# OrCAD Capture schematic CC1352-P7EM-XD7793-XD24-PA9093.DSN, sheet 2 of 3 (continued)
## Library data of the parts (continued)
L33 L42 = INDUCTOR_HOR_1_2: INDUCTOR, RF, CHIP, NON-MAGNETIC CORE, 10nH, -5%/+5%, 0.3A, -55DEGC/+125DEGC, 0402, SMD; ALT_SYMBOLS: INDC1005X60C2L,INDC1005X60C2M; Additional Datasheet URL: https://search.murata.co.jp/Ceramy/image/img/P02/JELF243B-0010.pdf; Budgetary Price: 0.03 EUR; Country of Origin: Japan,Singapore; Datasheet URL: https://www.murata.com/~/media/webrenewal/support/library/catalog/products/inductor/chip/o05e.ashx?la=en-gb; FPLIST: INDC1005X60C2N,INDC1005X60D2N; Frequency: 3.4GHz; Lead Time: 9; Mass: 0.001g; Maximum Operating Temperature: +125DEGC; Maximum Tolerance: +5%; Minimum Operating Temperature: -55DEGC; Minimum Tolerance: -5%; Mounting Type: SMD; NOTEfied URL: https://notefied-dynamic-precision.com/NOTEfiedWebInterface/part/show?partNumber=03-06635; PCB Package: 0402; Packing Size: 10000; Packing Type: Tape & Reel; Part Number: 03-06635; Part Type: Inductor|RF|CHIP|0402; REACH/SVHC Compliance: Compliant; REACH/SVHC Details: SVHC List Version Jul 7, 2017; REACH/SVHC Source: REACH Declaration; REACH/SVHC Status: Unaffected; ROHS: Compliant; Resistance: 0.26; Revision: R016; Status: Released; Texas Part Status: Under Review; Type: Inductor; Vendor: MURATA; Vendor Part Number: LQG15HS10NJ02D; Vendor Part Status: Active
L34 = INDUCTOR_HOR_1_2: INDUCTOR, RF, CHIP, NON-MAGNETIC CORE, 7.5nH, -5%/+5%, 0.3A, -55DEGC/+125DEGC, 0402, SMD; Additional Datasheet URL: https://search.murata.co.jp/Ceramy/image/img/P02/JELF243B-0010.pdf; Budgetary Price: 0.03 EUR; Country of Origin: Missing Info; Datasheet URL: https://www.murata.com/~/media/webrenewal/support/library/catalog/products/inductor/chip/o05e.ashx?la=en-gb; Frequency: 4.2GHz; Lead Time: 10; Mass: 0.001g; Maximum Operating Temperature: +125DEGC; Maximum Tolerance: +5%; Minimum Operating Temperature: -55DEGC; Minimum Tolerance: -5%; Mounting Type: SMD; NOTEfied URL: https://notefied-dynamic-precision.com/NOTEfiedWebInterface/part/show?partNumber=03-07022; PCB Package: 0402; Packing Size: 10000; Packing Type: Tape & Reel; Part Number: 03-07022; Part Type: Inductor|RF|CHIP|0402; REACH/SVHC Compliance: Compliant; REACH/SVHC Details: SVHC List Version Jul 7, 2017; REACH/SVHC Source: REACH Declaration; REACH/SVHC Status: Unaffected; ROHS: Compliant; Resistance: 0.24; Revision: R017; Status: Released; Texas Part Status: Under Review; Type: Inductor; Vendor: MURATA; Vendor Part Number: LQG15HS7N5J02D; Vendor Part Status: Active
L51 L61 = INDUCTOR_HOR_1_2: INDUCTOR, RF, CHIP, NON-MAGNETIC CORE, 1nH, -0.3nH/+0.3nH, 0.3A, -55DEGC/+125DEGC, 0402, SMD; ALT_SYMBOLS: INDC1005X60C2L,INDC1005X60C2M; Additional Datasheet URL: https://search.murata.co.jp/Ceramy/image/img/P02/JELF243B-0010.pdf; Budgetary Price: 0.031 EUR; Country of Origin: Japan,Singapore; Datasheet URL: https://www.murata.com/~/media/webrenewal/support/library/catalog/products/inductor/chip/o05e.ashx?la=en-gb; Frequency: 10GHz; Lead Time: 9; Mass: 0.001g; Maximum Operating Temperature: +125DEGC; Maximum Tolerance: +0.3nH; Minimum Operating Temperature: -55DEGC; Minimum Tolerance: -0.3nH; Mounting Type: SMD; NOTEfied URL: https://notefied-dynamic-precision.com/NOTEfiedWebInterface/part/show?partNumber=03-07676; PCB Package: 0402; Packing Size: 10000; Packing Type: Tape & Reel; Part Number: 03-07676; Part Type: Inductor|RF|CHIP|0402; REACH/SVHC Compliance: Compliant; REACH/SVHC Details: SVHC List Version Jul 7, 2017; REACH/SVHC Source: REACH Declaration; REACH/SVHC Status: Unaffected; ROHS: Compliant; Resistance: 0.07; Revision: R018; Status: Released; Texas Part Status: Under Review; Type: Inductor; Vendor: MURATA; Vendor Part Number: LQG15HS1N0S02D; Vendor Part Status: Active
L52 = INDUCTOR_HOR_1_2: INDUCTOR, RF, CHIP, NON-MAGNETIC CORE, 27nH, -5%/+5%, 0.3A, -55DEGC/+125DEGC, 0402, SMD; Additional Datasheet URL: https://search.murata.co.jp/Ceramy/image/img/P02/JELF243B-0010.pdf; Budgetary Price: 0.03 EUR; Country of Origin: Japan,Singapore; Datasheet URL: https://www.murata.com/~/media/webrenewal/support/library/catalog/products/inductor/chip/o05e.ashx?la=en-gb; Exclusive for Customers: TEXAS INSTRUMENTS NORWAY; Frequency: 1700MHz; Lead Time: 9; Mass: 0.001g; Maximum Operating Temperature: +125DEGC; Maximum Tolerance: +5%; Minimum Operating Temperature: -55DEGC; Minimum Tolerance: -5%; Mounting Type: SMD; NOTEfied URL: https://notefied-dynamic-precision.com/NOTEfiedWebInterface/part/show?partNumber=03-07528; Notes: Standard item: Duplicate Reason: custom footprint for TEXAS INSTRUMENTS NORWAY.; PCB Package: 0402; Packing Size: 10000; Packing Type: Tape & Reel; Part Number: 03-07528; Part Type: Inductor|RF|CHIP|0402; REACH/SVHC Compliance: Compliant; REACH/SVHC Details: SVHC List Version Jul 7, 2017; REACH/SVHC Source: REACH Declaration; REACH/SVHC Status: Unaffected; ROHS: Compliant; Resistance: 0.46; Revision: R018; Status: Released; Texas Part Status: Under Review; Type: Inductor; Vendor: MURATA; Vendor Part Number: LQG15HS27NJ02D; Vendor Part Status: Active
L53 L62 = INDUCTOR: INDUCTOR, RF, CHIP, NON-MAGNETIC CORE, 12nH, -5%/+5%, 0.5A, -55DEGC/+125DEGC, 0402, SMD; ALT_SYMBOLS: INDC1005X60A2L,INDC1005X60A2M; Additional Datasheet URL: https://search.murata.co.jp/Ceramy/image/img/P02/JELF243A-0050.pdf; AutoDoc File: https://notefied-dynamic-precision.com/DB/Apps/Desktop/Item/Object.aspx?id=86088; BU Name: DYNAMIC PRECISION GDANSK; Budget Currency: EUR; Budget Price: 0.144; Budgetary Price: 0.144 EUR; Client Status: UNDER_REVIEW; Core Material: NON-MAGNETIC; Country of Origin: Japan,Singapore; Datasheet URL: https://www.murata.com/~/media/webrenewal/support/library/catalog/products/inductor/chip/o05e.ashx?la=en-gb; Datasheet URL 1: http://psearch.murata.com/inductor/product/LQW15AN12NJ00%23.pdf; Datasheet URL 2: http://www.murata.com/~/media/webrenewal/support/library/catalog/products/inductor/chip/o05e.ashx; FPLIST: INDC1005X60A2N,INDC1005X60B2N; Frequency: 5.5GHz; Lead Time: 9; Mass: 0.0008g; Max Oper Temp: +125DEGC; Max Tol: +5%; Maximum Operating Temperature: +125DEGC; Maximum Tolerance: +5%; Min Oper Temp: -55DEGC; Min Tol: -5%; Minimum Operating Temperature: -55DEGC; Minimum Tolerance: -5%; Mounting Type: SMD; NOTEfied URL: https://notefied-dynamic-precision.com/NOTEfiedWebInterface/part/show?partNumber=03-06556; PCB Package: 0402; Packing Size: 10000; Packing Type: Tape & Reel; Part Number: 03-06556; Part Type: Inductor|RF|CHIP|0402; REACH/SVHC Compliance: Compliant; REACH/SVHC Details: SVHC List Version Jul 7, 2017; REACH/SVHC Source: REACH Declaration; REACH/SVHC Status: Unaffected; REACH/SVHC_COMPLIANCE: COMPLIANT; REACH/SVHC_DETAILS: SVHC LIST VERSION Dec 17, 2015; REACH/SVHC_SOURCE: REACH DECLARATION; REACH/SVHC_STATUS: UNAFFECTED; ROHS: Compliant; Resistance: 0.14; Revision: R021; RoHS Status: ROHS_COMPLIANT; Rtd Current: 0.5A; Status: Released; Texas Part Status: Under Review; Type: Inductor; Vendor: MURATA; Vendor Part Number: LQW15AN12NJ00D; Vendor Part Status: Active; Weight: 0.0008g
L54 = INDUCTOR: INDUCTOR, RF, CHIP, NON-MAGNETIC CORE, 4.3nH, -0.2nH/+0.2nH, 0.75A, -55DEGC/+125DEGC, 0402, SMD; ALT_SYMBOLS: INDC1005X60A2L,INDC1005X60A2M; Additional Datasheet URL: https://search.murata.co.jp/Ceramy/image/img/P02/JELF243A-0050.pdf; AutoDoc File: https://notefied-dynamic-precision.com/DB/Apps/Desktop/Item/Object.aspx?id=88050; BU Name: DYNAMIC PRECISION GDANSK; Budget Currency: EUR; Budget Price: 0.151; Budgetary Price: 0.151 EUR; Client Status: UNDER_REVIEW; Core Material: NON-MAGNETIC; Country of Origin: Japan,Singapore; Datasheet URL: https://www.murata.com/~/media/webrenewal/support/library/catalog/products/inductor/chip/o05e.ashx?la=en-gb; Datasheet URL 1: http://psearch.murata.com/inductor/product/LQW15AN4N3C00%23.pdf; Datasheet URL 2: http://www.murata.com/~/media/webrenewal/support/library/catalog/products/inductor/chip/o05e.ashx; FPLIST: INDC1005X60A2N,INDC1005X60B2N; Frequency: 10GHz; Lead Time: 9; Mass: 0.0008g; Max Oper Temp: +125DEGC; Max Tol: +0.2nH; Maximum Operating Temperature: +125DEGC; Maximum Tolerance: +0.2nH; Min Oper Temp: -55DEGC; Min Tol: -0.2nH; Minimum Operating Temperature: -55DEGC; Minimum Tolerance: -0.2nH; Mounting Type: SMD; NOTEfied URL: https://notefied-dynamic-precision.com/NOTEfiedWebInterface/part/show?partNumber=03-06658; PCB Package: 0402; Packing Size: 10000; Packing Type: Tape & Reel; Part Number: 03-06658; Part Type: Inductor|RF|CHIP|0402; REACH/SVHC Compliance: Compliant; REACH/SVHC Details: SVHC List Version Jan 15, 2018; REACH/SVHC Source: REACH Declaration; REACH/SVHC Status: Unaffected; ROHS: Compliant; Resistance: 0.07; Revision: R019; RoHS Status: ROHS_COMPLIANT; Rtd Current: 0.75A; Status: Released; Texas Part Status: Under Review; Type: Inductor; Vendor: MURATA; Vendor Part Number: LQW15AN4N3C00D; Vendor Part Status: Active; Weight: 0.0008g
L55 = INDUCTOR: INDUCTOR, RF, CHIP, NON-MAGNETIC CORE, 2.5nH, -0.2nH/+0.2nH, 0.85A, -55DEGC/+125DEGC, 0402, SMD; ALT_SYMBOLS: INDC1005X60A2L,INDC1005X60A2M; Additional Datasheet URL: https://search.murata.co.jp/Ceramy/image/img/P02/JELF243A-0050.pdf; AutoDoc File: https://notefied-dynamic-precision.com/DB/Apps/Desktop/Item/Object.aspx?id=88045; BU Name: DYNAMIC PRECISION GDANSK; Budget Currency: EUR; Budget Price: 0.151; Budgetary Price: 0.151 EUR; Client Status: UNDER_REVIEW; Core Material: NON-MAGNETIC; Country of Origin: Japan,Singapore; Datasheet URL: https://www.murata.com/~/media/webrenewal/support/library/catalog/products/inductor/chip/o05e.ashx?la=en-gb; Datasheet URL 1: http://psearch.murata.com/inductor/product/LQW15AN2N5C00%23.pdf; Datasheet URL 2: http://www.murata.com/~/media/webrenewal/support/library/catalog/products/inductor/chip/o05e.ashx; FPLIST: INDC1005X60A2N,INDC1005X60B2N; Frequency: 15GHz; Lead Time: 10; Mass: 0.0008g; Max Oper Temp: +125DEGC; Max Tol: +0.2nH; Maximum Operating Temperature: +125DEGC; Maximum Tolerance: +0.2nH; Min Oper Temp: -55DEGC; Min Tol: -0.2nH; Minimum Operating Temperature: -55DEGC; Minimum Tolerance: -0.2nH; Mounting Type: SMD; NOTEfied URL: https://notefied-dynamic-precision.com/NOTEfiedWebInterface/part/show?partNumber=03-06653; PCB Package: 0402; Packing Size: 10000; Packing Type: Tape & Reel; Part Number: 03-06653; Part Type: Inductor|RF|CHIP|0402; REACH/SVHC Compliance: Compliant; REACH/SVHC Details: SVHC List Version Jan 15, 2018; REACH/SVHC Source: REACH Declaration; REACH/SVHC Status: Unaffected; ROHS: Compliant; Resistance: 0.05; Revision: R020; RoHS Status: ROHS_COMPLIANT; Rtd Current: 0.85A; Status: Released; Texas Part Status: Under Review; Type: Inductor; Vendor: MURATA; Vendor Part Number: LQW15AN2N5C00D; Vendor Part Status: Active; Weight: 0.0008g
L56 = INDUCTOR: INDUCTOR, RF, CHIP, NON-MAGNETIC CORE, 4.7nH, -0.2nH/+0.2nH, 0.75A, -55DEGC/+125DEGC, 0402, SMD; ALT_SYMBOLS: INDC1005X60A2L,INDC1005X60A2M; Additional Datasheet URL: https://search.murata.co.jp/Ceramy/image/img/P02/JELF243A-0050.pdf; AutoDoc File: https://notefied-dynamic-precision.com/DB/Apps/Desktop/Item/Object.aspx?id=88051; BU Name: DYNAMIC PRECISION GDANSK; Budget Currency: EUR; Budget Price: 0.152; Budgetary Price: 0.152 EUR; Client Status: UNDER_REVIEW; Core Material: NON-MAGNETIC; Country of Origin: Japan,Singapore; Datasheet URL: https://www.murata.com/~/media/webrenewal/support/library/catalog/products/inductor/chip/o05e.ashx?la=en-gb; Datasheet URL 1: http://psearch.murata.com/inductor/product/LQW15AN4N7C00%23.pdf; Datasheet URL 2: http://www.murata.com/~/media/webrenewal/support/library/catalog/products/inductor/chip/o05e.ashx; FPLIST: INDC1005X60A2N,INDC1005X60B2N; Frequency: 8GHz; Lead Time: 9; Mass: 0.0008g; Max Oper Temp: +125DEGC; Max Tol: +0.2nH; Maximum Operating Temperature: +125DEGC; Maximum Tolerance: +0.2nH; Min Oper Temp: -55DEGC; Min Tol: -0.2nH; Minimum Operating Temperature: -55DEGC; Minimum Tolerance: -0.2nH; Mounting Type: SMD; NOTEfied URL: https://notefied-dynamic-precision.com/NOTEfiedWebInterface/part/show?partNumber=03-06659; PCB Package: 0402; Packing Size: 10000; Packing Type: Tape & Reel; Part Number: 03-06659; Part Type: Inductor|RF|CHIP|0402; REACH/SVHC Compliance: Compliant; REACH/SVHC Details: SVHC List Version Jan 15, 2018; REACH/SVHC Source: REACH Declaration; REACH/SVHC Status: Unaffected; ROHS: Compliant; Resistance: 0.07; Revision: R019; RoHS Status: ROHS_COMPLIANT; Rtd Current: 0.75A; Status: Released; Texas Part Status: Under Review; Type: Inductor; Vendor: MURATA; Vendor Part Number: LQW15AN4N7C00D; Vendor Part Status: Active; Weight: 0.0008g
L331 = INDUCTOR: INDUCTOR, STANDARD, FERRITE CORE, 6.8uH, -20%/+20%, 0.11A, -55DEGC/+125DEGC, 0805, SMD; ALT_SYMBOLS: INDC2012X150A2L,INDC2012X150A2M; Additional Datasheet URL: https://product.tdk.com/en/search/inductor/inductor/smd/info?part_no=MLZ2012N6R8LT000; AutoDoc File: https://notefied-dynamic-precision.com/DB/Apps/Desktop/Item/Object.aspx?id=102853; BU Name: DYNAMIC PRECISION GDANSK; Budget Currency: EUR; Budget Price: 0.059; Budgetary Price: 0.045 USD; Client Status: UNDER_REVIEW; Core Material: FERRITE; Country of Origin: Missing Info; Datasheet URL: http://product.tdk.com/info/en/catalog/datasheets/inductor_commercial_decoupling_mlz2012_en.pdf; Datasheet URL 1: https://product.tdk.com/info/en/catalog/datasheets/inductor_commercial_decoupling_mlz2012_en.pdf; Datasheet URL 2: N/A; Lead Time: 10; MPN: MLZ2012N6R8LT000; MPN Status: ACTIVE; Manufacturer: TDK; Mass: 0.01g; Max Oper Temp: +125DEGC; Max Tol: +20%; Maximum Operating Temperature: +125DEGC; Maximum Tolerance: +20%; Min Oper Temp: -55DEGC; Min Tol: -20%; Minimum Operating Temperature: -55DEGC; Minimum Tolerance: -20%; Mounting Type: SMD; NOTE Status: PREFERRED; NOTEfied URL: https://notefied-dynamic-precision.com/NOTEfiedWebInterface/part/show?partNumber=03-07266; Old Footprint: INDC2012X150N; PCB Package: 0805; Packing Size: 4000; Packing Type: Tape & Reel; Part Number: 03-07266; Part Type: Inductor|STANDARD|CHIP|0805; REACH/SVHC Compliance: Compliant; REACH/SVHC Details: SVHC List Version Jan 12, 2017; REACH/SVHC Source: REACH Declaration; REACH/SVHC Status: Unaffected; REACH/SVHC_COMPLIANCE: COMPLIANT; REACH/SVHC_DETAILS: SVHC LIST VERSION Dec 17, 2015; REACH/SVHC_SOURCE: REACH DECLARATION; REACH/SVHC_STATUS: UNAFFECTED; ROHS: Compliant; Resistance: 0.25; Revision: R014; RoHS Status: ROHS_COMPLIANT; Rtd Current: 1.1A; Status: Released; Texas Part Status: Under Review; Type: Inductor; Vendor: TDK; Vendor Part Number: MLZ2012N6R8LT000; Vendor Part Status: Active; WEIGHT: 0.01g
P1 P2 = CONN_HEADER_2X10_P_S: CONNECTOR, HEADER, FEMALE, STRAIGHT, 2 ROWS, 20 PINS, PITCH 1.27mm, SMD; ALT_SYMBOLS: SAMTEC_SFM11002AL,SAMTEC_SFM11002AM; Additional Datasheet URL: http://suddendocs.samtec.com/prints/sfm-1xx-xx-xxx-d-xxx-mkt.pdf; Alt IPC Footprints: SAMTEC_SFM11002AL,SAMTEC_SFM11002AM; AutoDoc File: https://notefied-dynamic-precision.com/DB/Apps/Desktop/Item/Object.aspx?id=85603; BU Name: TEXAS INSTRUMENTS NORWAY; Budget Currency: USD; Budget Price: 3.180; Budgetary Price: 5.3504 USD; CLASS: IO; Client Status: UNDER_REVIEW; Country of Origin: China,Costa Rica,Malaysia,Singapore,United States; Datasheet URL: http://suddendocs.samtec.com/catalog_english/sfm.pdf; Datasheet URL 1: http://suddendocs.samtec.com/catalog_english/sfm.pdf; Datasheet URL 2: http://suddendocs.samtec.com/prints/sfm-1xx-xx-xxx-d-xxx-mkt.pdf; Lead Time: 4; MPN: SFM-110-02-SM-D-A-K-TR; MPN Status: ACTIVE; Manufacturer: SAMTEC; Mass: 0.30875g; Max Oper Temp: +125DEGC; Maximum Operating Temperature: +125DEGC; Min Oper Temp: -55DEGC; Minimum Operating Temperature: -55DEGC; Mounting Type: SMD; NOTE Status: PREFERRED; NOTEfied URL: https://notefied-dynamic-precision.com/NOTEfiedWebInterface/part/show?partNumber=06-02251; No Of Pos: 20; No Of Rows: 2; Number of Positions: 20; Number of Rows: 2; Packing Size: 725; Packing Type: Tape & Reel; Part Number: 06-02251; Part Type: Connector|HEADER|STANDARD; Pitch: 1.27mm; REACH/SVHC Compliance: Compliant; REACH/SVHC Details: SVHC List Version Jan 12, 2017; REACH/SVHC Source: Material Declaration; REACH/SVHC Status: Unaffected; ROHS: Compliant; Revision: R013; RoHS Status: ROHS_COMPLIANT; Status: Released; Texas Part Status: Under Review; Type: Connector; Vendor: SAMTEC; Vendor Part Number: SFM-110-02-SM-D-A-K-TR; Vendor Part Status: Active; Weight: 0.30875g
R351 = RESISTOR: RESISTOR, THICK FILM, 100k, -5%/+5%, 0.063W, 50V, -55DEGC/+155DEGC, 0402, SMD; Additional Datasheet URL: N/A; AutoDoc File: https://notefied-dynamic-precision.com/DB/Apps/Desktop/Item/Object.aspx?id=114565; BU Name: TEXAS INSTRUMENTS NORWAY; Budget Currency: EUR; Budget Price: 0.014; Budgetary Price: 0.014 EUR; Client Status: UNDER_REVIEW; Country of Origin: United States; Datasheet URL: https://www.vishay.com/docs/20035/dcrcwe3.pdf; Datasheet URL 1: http://www.vishay.com/docs/20035/dcrcwe3.pdf; Datasheet URL 2: N/A; Definied Quality: INDUSTRIAL; Esd Level: N/A; Exclusive for Customers: TEXAS INSTRUMENTS NORWAY; Lead Time: 18; LifeCycle Status: ACTIVE; MPN: RESISTOR_0402_100k_+/-1%_50V_0.063W_M_+/-100PPM; MPN Status: ACTIVE; MSL: N/A; MTBF: N/A; MTBF Standard: N/A; Manufacturer: MANUFACTURER SELECTION; Mass: 0.00065g; Max Oper Temp: +155DEGC; Max TC: +200PPM/DEGC; Max Tol: +5%; Maximum Operating Temperature: +155DEGC; Maximum Temperature Coefficient: +200PPM/DEGC; Maximum Tolerance: +5%; Min Oper Temp: -55DEGC; Min TC: -200PPM/DEGC; Min Tol: -5%; Minimum Operating Temperature: -55DEGC; Minimum Temperature Coeficient: -200PPM/DEGC; Minimum Tolerance: -5%; Mounting Type: SMD; NOTE Status: PREFERRED; NOTEfied URL: https://notefied-dynamic-precision.com/NOTEfiedWebInterface/part/show?partNumber=01-22492; Notes: Standard item: Duplicate Reason: custom footprint for TEXAS INSTRUMENTS NORWAY.; Old Footprint: RESC1005X40N; PCB Package: 0402; Packing Size: 10000; Packing Type: Tape & Reel; Part Number: 01-22492; Part Type: Resistor|0402|STANDARD; REACH/SVHC Compliance: Compliant; REACH/SVHC Details: SVHC List Version Jun 20, 2016; REACH/SVHC Source: Material Declaration; REACH/SVHC Status: Unaffected; REACH/SVHC_COMPLIANCE: COMPLIANT; REACH/SVHC_DETAILS: SVHC LIST VERSION Jun 20, 2016; REACH/SVHC_SOURCE: MATERIAL DECLARATION; REACH/SVHC_STATUS: UNAFFECTED; ROHS: Exempt; Rated Current: N/A; Rated Power: 0.063W; Rated Voltage: 50V; Resistor Type: THICK FILM; Revision: R014; RoHS Status: ROHS_COMPLIANT; Rtd Current: N/A; Rtd Power: 0.063W; Rtd Voltage: 50V; Status: Released; Texas Part Status: Under Review; Type: Resistor; Vendor: VISHAY; Vendor Part Number: CRCW0402100KJNED; Vendor Part Status: Active; WEIGHT: 0.00065g
U1 = IC_RF_CC1352P1F64_QFN48: IC, MICROCONTROLLER, TEXAS INSTRUMENTS, ARM CORTEX M4F, HIGH-PERFORMANCE DUAL-BAND WIRELESS MCU WITH INTEGRATED POWER AMPLIFIER, 1.8V TO 3.8V, VQFN48-EP, SMD; ALT_SYMBOLS: QFNFC50P700X700X100-49A2L,QFNFC50P700X700X100-49A2M; Additional Datasheet URL: N/A; Datasheet URL: https://www.ti.com/; Exclusive for Customers: TEXAS INSTRUMENTS NORWAY; Frequency: 48MHz; Mass: N/A; Maximum Operating Temperature: +85DEGC; Minimum Operating Temperature: -40DEGC; Mounting Type: SMD; NOTEfied URL: https://notefied-dynamic-precision.com/NOTEfiedWebInterface/part/show?partNumber=18-36101; Notes: Preliminary item, please check if it apperas on the website.; PCB Package: VQFN48-EP; Packing Size: N/A; Packing Type: Missing Info; Part Number: 18-36101; Part Type: IC|MICROCONTROLLER|TEXAS INSTRUMENTS; REACH/SVHC Compliance: Missing Info; REACH/SVHC Details: N/A; REACH/SVHC Source: N/A; REACH/SVHC Status: Missing Info; ROHS: Compliant; Rated Voltage: 1.8V TO 3.8V; Revision: R003; Status: Released; Texas Part Status: Under Review; Type: IC; Vendor: TEXAS INSTRUMENTS; Vendor Part Status: Preliminary
U2 = IC_RF_SKY13317-373LF_MLP8: IC, ANALOG, RF, SWITCH,  20MHz TO 6GHz, SP3T, VCONTROL:0V TO 5V, MLP8-EP, SMD; Additional Datasheet URL: http://www.skyworksinc.com/Product/586/SKY13317-373LF; Budgetary Price: 0.844 EUR; CLASS: IO; Datasheet URL: http://www.skyworksinc.com/uploads/documents/SKY13317_373LF_200914K.pdf; Frequency: 20MHz TO 6GHz; Lead Time: 2; Mass: N/A; Maximum Operating Temperature: +100DEGC; Minimum Operating Temperature: -40DEGC; Mounting Type: SMD; NOTEfied URL: https://notefied-dynamic-precision.com/NOTEfiedWebInterface/part/show?partNumber=18-33966; PCB Package: MLP8-EP; Packing Size: N/A; Packing Type: Tape & Reel; Part Number: 18-33966; Part Type: IC|ANALOG|RF|SWITCH; REACH/SVHC Compliance: Compliant; REACH/SVHC Details: SVHC List Version Dec 19, 2012; REACH/SVHC Source: REACH Declaration; REACH/SVHC Status: Unaffected; ROHS: Compliant; Rated Voltage: 0V TO 5V; Revision: R010; Status: Released; Texas Part Status: Under Review; Type: IC; Vendor: SKYWORKS; Vendor Part Number: SKY13317-373LF; Vendor Part Status: Active
Y1 = XTAL: CRYSTAL, RESONATOR, 32.768kHz, -40DEGC/+125DEGC, SMD; ALT_SYMBOLS: XTAL_TZ1166C_A2L,XTAL_TZ1166C_A2M; Capacitance: 7pF; Datasheet URL: https://www.taisaw.com/en/product.php?pc=7; Exclusive for Customers: TEXAS INSTRUMENTS NORWAY; Maximum Operating Temperature: +125DEGC; Maximum Stability: N/A; Maximum Tolerance: +20PPM; Minimum Operating Temperature: -40DEGC; Minimum Stability: N/A; Minimum Tolerance: -20PPM; Mounting Type: SMD; NOTEfied URL: https://notefied-dynamic-precision.com/NOTEfiedWebInterface/part/show?partNumber=12-01495; Notes: Non-standard part/non-catalogue part. Created on the basis of documentation provided by the customer (Texas Instruments).; Packing Size: 3000; Packing Type: Tape & Reel; Part Number: 12-01495; Part Type: Crystal|RESONATOR; REACH/SVHC Compliance: Missing Info; REACH/SVHC Details: N/A; REACH/SVHC Source: N/A; REACH/SVHC Status: Missing Info; ROHS: Compliant; Revision: R001; Status: Released; Texas Part Status: Under Review; Type: Crystal; Vendor: TAI-SAW; Vendor Part Number: TZ1166C; Vendor Part Status: Active
Y2 = XTAL_4_V3: CRYSTAL, RESONATOR, 48MHz, -16PPM/+16PPM, -40DEGC/+105DEGC, SMD; ALT_SYMBOLS: OSCCC200X160X50-4A2L,OSCCC200X160X50-4A2M; Capacitance: 7pF; Datasheet URL: https://www.taisaw.com/en/product.php?pc=7; Exclusive for Customers: TEXAS INSTRUMENTS NORWAY; Mass: 0.0057g; Maximum Operating Temperature: +105DEGC; Maximum Stability: +16PPM; Maximum Tolerance: +8PPM; Minimum Operating Temperature: -40DEGC; Minimum Stability: -16PPM; Minimum Tolerance: -8PPM; Mounting Type: SMD; NOTEfied URL: https://notefied-dynamic-precision.com/NOTEfiedWebInterface/part/show?partNumber=12-01494; Notes: Non-standard part/non-catalogue part. Created on the basis of documentation provided by the customer (Texas Instruments).; Packing Size: 3000; Packing Type: Tape & Reel; Part Number: 12-01494; Part Type: Crystal|RESONATOR; REACH/SVHC Compliance: Missing Info; REACH/SVHC Details: N/A; REACH/SVHC Source: N/A; REACH/SVHC Status: Missing Info; ROHS: Compliant; Revision: R001; Status: Released; Texas Part Status: Under Review; Type: Crystal; Vendor: TAI-SAW; Vendor Part Number: TZ2365C; Vendor Part Status: Active

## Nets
GND: C1.2 C11.2 C13.2 C14.2 C21.2 C32.2 C34.2 C35.2 C41.2 C51.1 C52.2 C54.2 C57.2 C61.1 C81.2 C91.2 C131.2 C221.2 C231.2 C331.2 C341.2 C342.2 C351.2 C441.2 C451.2 C461.2 C471.2 C481.2 CR13.1 J1.2 J1.3 J1.4 J1.5 L55.2 P1.1 P1.19 P2.2 P2.20 U1.49(EGP) U2.9(EGP) Y2.2(GND) Y2.4(GND) ; also on sheet 1
VDD_EB: FL1.2 P2.7 P2.9
VDDR: C331.1 C451.1 C481.1 L331.2 U1.45(VDDR) U1.48(VDDR_RF)
VDDS: C1.1 C51.2 C52.1 C131.1 C221.1 C341.1 C342.1 C441.1 FL1.1 L53.1 R351.2 U1.13(VDDS2) U1.22(VDDS3) U1.34(VDDS_DCDC) U1.44(VDDS)
DCDC_SW: L331.1 U1.33(DCDC_SW)
DIO_5: P1.13 U1.10(DIO_5)
DIO_6: P1.4 U1.11(DIO_6)
DIO_7: P1.2 U1.12(DIO_7)
DIO_8: P1.20 U1.14(DIO_8)
DIO_9: P1.18 U1.15(DIO_9)
DIO_10: P1.16 U1.16(DIO_10)
DIO_11: P1.14 U1.17(DIO_11)
DIO_12: P1.12 U1.18(DIO_12)
DIO_13: P1.15 U1.19(DIO_13)
DIO_14: P1.17 U1.20(DIO_14)
DIO_15: P1.6 U1.21(DIO_15)
DIO_16 / JTAG TDO: P2.19 U1.26(DIO_16)
DIO_17 / JTAG TDI: P2.17 U1.27(DIO_17)
DIO_18: P1.8 U1.28(DIO_18)
DIO_19: P1.10 U1.29(DIO_19)
DIO_20: P2.8 U1.30(DIO_20)
DIO_21: P2.18 U1.31(DIO_21)
DIO_22: P1.3 U1.32(DIO_22)
DIO_23: P2.5 U1.36(DIO_23)
DIO_24: P2.10 U1.37(DIO_24)
DIO_25: P2.11 U1.38(DIO_25)
DIO_26: P2.6 U1.39(DIO_26)
DIO_27: P2.13 U1.40(DIO_27)
DIO_28: U1.41(DIO_28) U2.7(V3)
DIO_29: U1.42(DIO_29) U2.3(V1)
DIO_30: U1.43(DIO_30) U2.6(V2)
JTAG_TCK: P2.1 U1.25(JTAG_TCKC)
JTAG_TMS: P2.4 U1.24(JTAG_TMSC)
nRESET: C351.1 P2.15 R351.1 U1.35(RESET_N)
RX_TX: C11.1 C32.1 L12.2 L33.1 U1.7(RX_TX)
N485531: C37.1 U2.5(RF2)
N485533: C482.2 J1.1
N485663: C33.2 C34.1 L34.1 L42.2
N485699: C231.1 U1.23(DCOUPL)
N485701: C81.1 U1.8(X32K_Q1) Y1.1
N485707: C91.1 U1.9(X32K_Q2) Y1.2
N485827: C35.1 C37.2 L34.2
N485903: C31.1 C33.1 L31.2 L32.1 L33.2
N501959: C471.1 U1.47(X48M_P) Y2.1
N501977: C461.1 U1.46(X48M_N) Y2.3
N512033: C12.2 L13.1 L21.2
N512042: C13.1 L13.2 L14.1
N512564: C15.2 U2.8(RF3)
N513741: C21.1 L11.2 L21.1 U1.2(2_4_GHZ_RF_N)
N516755: C31.2 C41.1 L32.2 L41.2 L42.1
N517773: C53.1 L51.2 L52.1 L53.2
N517777: C61.2 L52.2 L61.2 L62.1
N517801: C53.2 C54.1 C55.1 L54.1 L62.2
N517942: C55.2 C56.1 L54.2 L56.1
N518069: C57.1 C58.1 L56.2
N553230: C14.1 C15.1 L14.2
N561899: L61.1 U1.6(TX_20DBM_N)
N583447: C482.1 CR13.2 U2.1(RFC)
N583481: C58.2 U2.4(RF1)
N2475876: L51.1 U1.5(TX_20DBM_P)
N2475926: L41.1 U1.4(SUB-1_GHZ_RF_N)
N2476223: L31.1 U1.3(SUB-1_GHZ_RF_P)
N2476600: C12.1 L11.1 L12.1 U1.1(2_4_GHZ_RF_P)
N2490884: C56.2 L55.1

Not connected (* = marked no-connect by the designer): P1 5* 7* 9* 11*; P2 3* 12* 14* 16*; U2 2(NC)

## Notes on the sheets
sheet 2
- VDDR Decoupling Capacitors
- VDDS Decoupling Capacitors
- Pin 13
- Pin 22
- Pin 44
- Pin 34
- Pin 45
- Pin 48
- Place L331 and C331 close to pin 33.
  Low inductance ground for C331
- 5 dBm 2.4 GHz
- 14 dBm 770-930 MHz
- RF Control Truth Table
- DIO28 DIO29  DIO30
  Shutdown   0     0      0
  Sub 1 GHz  0     0      1
  20 dBm PA  0     1      0
  2.4 GHz    1     0      0
- 20 dBm 900-930 MHz
- EM connector 1
- EM connector 2
- a0132672
